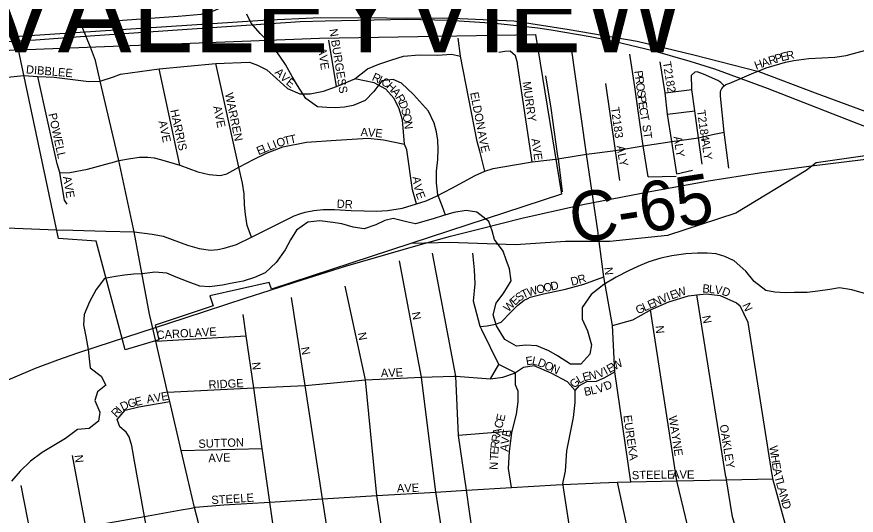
# Model space of a CAD drawing. Extents: x 0 to 34, y -6.2 to 22.
# Drawn here: x 2.51 to 3.469, y 17.811 to 18.38 of the extents above; entities that cross this region are included whole.
import ezdxf

# ---------------------------------------------------------------- set-up
doc = ezdxf.new("R2010")
doc.units = 0
for name, color, linetype in [('GM_X_City_Street', 7, 'Continuous'), ('GM_X_City_Street_Text', 7, 'Continuous'), ('GM_X_Corporation', 7, 'Continuous'), ('GM_X_Corporation_Text', 7, 'Continuous'), ('GM_X_County_Road', 7, 'Continuous'), ('GM_X_County_Road_Text', 7, 'Continuous'), ('GM_X_Minor_River', 7, 'Continuous'), ('GM_X_Rail_Line', 7, 'Continuous'), ('GM_X_Township_Road', 7, 'Continuous'), ('GM_X_Township_Subdivision', 7, 'Continuous'), ('GM_X_Township_Subdivision_Text', 7, 'Continuous')]:
    doc.layers.add(name, color=color, linetype=linetype)

msp = doc.modelspace()

# ---------------------------------------------------------------- linework, layer by layer
at = {"layer": 'GM_X_City_Street'}
for points in [[(2.58326, 18.37289), (2.69443, 18.38081), (2.72099, 18.38315), (2.73498, 18.38687), (2.78346, 18.40786), (2.87838, 18.44987), (3.04807, 18.52343), (3.04898, 18.52384), (3.12264, 18.55594), (3.17213, 18.57942), (3.21354, 18.59511), (3.23863, 18.6055), (3.35942, 18.6571)], [(2.58396, 18.37117), (2.58326, 18.37289), (2.54907, 18.44999), (2.51839, 18.50309), (2.51749, 18.50536)], [(3.35404, 18.31686), (3.35699, 18.31809), (3.36634, 18.32198), (3.3881, 18.32847), (3.39776, 18.3304), (3.41501, 18.33254), (3.44461, 18.33395), (3.45762, 18.33578), (3.47006, 18.33917), (3.48994, 18.34479), (3.54122, 18.36656), (3.5569, 18.37296), (3.56567, 18.37718), (3.57341, 18.38206), (3.58387, 18.39134)], [(2.66181, 18.0409), (2.64419, 18.13468), (2.64164, 18.14703), (2.62676, 18.21598), (2.60565, 18.30649), (2.60014, 18.33007), (2.59458, 18.34525), (2.59153, 18.35267)], [(2.87541, 18.30051), (2.86649, 18.35356)], [(3.04498, 18.20409), (3.03899, 18.22693), (3.03604, 18.23777), (3.01698, 18.33533), (3.01436, 18.3557)], [(3.08217, 18.32649), (3.08202, 18.32745), (3.08005, 18.33566), (3.07381, 18.34092), (3.06757, 18.34059), (3.06067, 18.33928)], [(2.51826, 18.31302), (2.53419, 18.31191), (2.55309, 18.31117), (2.59273, 18.30635), (2.60565, 18.30649), (2.62071, 18.31155), (2.62867, 18.3145), (2.67276, 18.3208), (2.7376, 18.32673), (2.7762, 18.32843), (2.78507, 18.32482), (2.79591, 18.31957), (2.80675, 18.30971), (2.81956, 18.29821), (2.83369, 18.2923), (2.84551, 18.2923), (2.86062, 18.29526), (2.87541, 18.30051), (2.89643, 18.30938), (2.91088, 18.32055), (2.92369, 18.32614), (2.93847, 18.33106), (2.95194, 18.33533), (2.96968, 18.33665), (2.99071, 18.33632), (3.0068, 18.3373), (3.01698, 18.33533)], [(2.69666, 18.21083), (2.67276, 18.3208)], [(2.77839, 18.1286), (2.77329, 18.14209), (2.77148, 18.15459), (2.77033, 18.1656), (2.77016, 18.17794), (2.76819, 18.1901), (2.76408, 18.20836), (2.7376, 18.32673)], [(3.09892, 18.21461), (3.08217, 18.32649)], [(2.41859, 18.30302), (2.42786, 18.30672), (2.49974, 18.31117), (2.51826, 18.31302)], [(2.55947, 18.20229), (2.55637, 18.21247), (2.53419, 18.31191)], [(2.96693, 18.16667), (2.96212, 18.18259), (2.95589, 18.22824), (2.95326, 18.23481), (2.95063, 18.26241), (2.94669, 18.2762), (2.9411, 18.28737), (2.93191, 18.29756), (2.91844, 18.30478), (2.89643, 18.30938)], [(2.61923, 18.21394), (2.62676, 18.21598), (2.64002, 18.21846), (2.65061, 18.21987), (2.66014, 18.22004), (2.66705, 18.21922), (2.67429, 18.21708), (2.69666, 18.21083), (2.71702, 18.20323), (2.72987, 18.19997), (2.7427, 18.19899), (2.7501, 18.2008), (2.76408, 18.20836), (2.78135, 18.21757), (2.79558, 18.22463), (2.81398, 18.23153), (2.84124, 18.23711), (2.87508, 18.23941), (2.91154, 18.24172), (2.92928, 18.23974), (2.95326, 18.23481)], [(2.57438, 18.13649), (2.61214, 18.13547), (2.64419, 18.13468), (2.66492, 18.13206), (2.67133, 18.13107), (2.67741, 18.12959), (2.70539, 18.11939), (2.71853, 18.11561), (2.7314, 18.11374), (2.7399, 18.11462), (2.74714, 18.1161), (2.76112, 18.12021), (2.77839, 18.1286), (2.82723, 18.1531), (2.83348, 18.15541), (2.83973, 18.15722), (2.8496, 18.15902), (2.86029, 18.16017), (2.87328, 18.16001), (2.89203, 18.15919), (2.90716, 18.15853), (2.92065, 18.1582), (2.9338, 18.15902), (2.95074, 18.16182), (2.96693, 18.16667), (2.97788, 18.17021), (2.98972, 18.1753), (3.00732, 18.18452), (3.03363, 18.19915), (3.04498, 18.20409), (3.05419, 18.20688), (3.06553, 18.20902), (3.09892, 18.21461), (3.12884, 18.2179), (3.13064, 18.21821)], [(2.55949, 18.2022), (2.57084, 18.20244), (2.59123, 18.20639), (2.61623, 18.21313), (2.61923, 18.21394)], [(2.56788, 18.16609), (2.56493, 18.17087), (2.55949, 18.2022), (2.55947, 18.20229)], [(2.27548, 18.14751), (2.34571, 18.14522), (2.55571, 18.13699), (2.57438, 18.13649)], [(3.24007, 17.60203), (3.22368, 17.69748), (3.21393, 17.76801), (3.19655, 17.84898), (3.21172, 17.84956), (3.19321, 17.97488), (3.19048, 18.02788), (3.1806, 18.08351), (3.17438, 18.13238), (3.17423, 18.13337)], [(3.05937, 17.59113), (3.03769, 17.7424), (3.02375, 17.83973), (3.01478, 17.90233), (3.01167, 17.96994), (2.98497, 18.11036)], [(3.04158, 18.02267), (3.03969, 18.02652), (3.03194, 18.05539), (3.03367, 18.07548), (3.033, 18.09147), (3.03128, 18.11052)], [(2.98919, 17.83622), (2.98896, 17.83766), (2.97268, 17.96886), (2.94752, 18.10159)], [(3.09407, 18.05875), (3.09668, 18.05996), (3.10426, 18.06213), (3.11184, 18.06375), (3.13701, 18.06916), (3.15786, 18.07485), (3.1806, 18.08351)], [(2.96334, 17.58694), (2.93742, 17.72782), (2.92149, 17.83363), (2.90852, 17.96561), (2.88548, 18.07284)], [(3.19048, 18.02788), (3.21388, 18.03445), (3.23279, 18.04491), (3.23418, 18.04554), (3.25509, 18.05489), (3.27731, 18.06184), (3.28691, 18.06282), (3.29749, 18.0639), (3.31375, 18.0619), (3.33211, 18.05376), (3.33655, 18.05021)], [(3.32028, 17.85514), (3.28691, 18.06282)], [(2.86019, 17.82555), (2.86019, 17.82555), (2.85952, 17.82993), (2.83954, 17.9594), (2.82408, 18.05962)], [(3.03969, 18.02652), (3.04767, 18.02747), (3.05701, 18.0295), (3.06351, 18.03153), (3.07448, 18.0429), (3.0826, 18.05089), (3.08964, 18.05671), (3.09407, 18.05875)], [(3.3066, 17.60722), (3.28493, 17.71335), (3.28155, 17.77778), (3.2641, 17.85059), (3.23418, 18.04554)], [(3.3733, 17.85605), (3.37312, 17.85724), (3.34549, 18.03133), (3.33655, 18.05021)], [(2.77221, 17.57666), (2.74444, 17.70037), (2.7131, 17.8201), (2.70525, 17.85431), (2.69807, 17.88511), (2.68501, 17.94112), (2.68256, 17.95161), (2.66897, 18.00986), (2.6621, 18.03937), (2.66181, 18.0409)], [(2.81498, 17.7179), (2.79947, 17.82635), (2.79072, 17.88755), (2.78086, 17.95649), (2.77232, 18.01618), (2.76887, 18.04034)], [(2.66897, 18.00986), (2.77232, 18.01618)], [(3.1351, 17.8404), (3.13477, 17.84263), (3.13422, 17.84621), (3.13402, 17.84753), (3.13701, 17.86138), (3.13864, 17.88466), (3.14622, 17.92283), (3.14812, 17.93989), (3.14812, 17.9537), (3.13918, 17.96344), (3.12062, 17.97335), (3.10128, 17.98185), (3.08909, 17.97969), (3.07989, 17.97373), (3.06094, 17.98321), (3.04158, 18.02267)], [(3.0512, 17.96696), (3.06094, 17.98321)], [(2.68256, 17.95161), (2.78086, 17.95649), (2.83954, 17.9594), (2.90852, 17.96561), (2.97268, 17.96886), (3.00935, 17.96988)], [(3.00935, 17.96988), (3.01167, 17.96994), (3.0512, 17.96696), (3.06554, 17.96872), (3.07989, 17.97373)], [(3.0754, 17.84281), (3.07189, 17.86457), (3.07285, 17.88392), (3.07574, 17.90512), (3.07625, 17.90723), (3.08092, 17.92663), (3.08285, 17.94063), (3.08283, 17.9528), (3.08141, 17.95626), (3.08001, 17.9601), (3.07989, 17.97373)], [(3.14812, 17.9537), (3.15286, 17.95948), (3.16133, 17.96378), (3.17235, 17.96422), (3.1812, 17.96814), (3.19321, 17.97488)], [(2.62493, 17.92068), (2.6341, 17.93099), (2.64974, 17.93496), (2.68501, 17.94112)], [(2.64391, 17.87736), (2.64151, 17.89055), (2.63878, 17.90089), (2.63513, 17.90594), (2.6281, 17.91223), (2.62493, 17.92068)], [(3.07625, 17.90723), (3.01478, 17.90233)], [(2.69807, 17.88511), (2.79072, 17.88755)], [(2.63357, 17.5687), (2.60917, 17.68894), (2.58905, 17.79807), (2.57401, 17.87961)], [(2.7, 17.57023), (2.67739, 17.69404), (2.65622, 17.81), (2.64396, 17.87712), (2.64391, 17.87736)], [(3.21172, 17.84956), (3.2641, 17.85059), (3.32083, 17.85171), (3.37382, 17.85275)], [(3.36005, 17.6082), (3.34153, 17.72315), (3.33463, 17.78614), (3.32761, 17.80952), (3.32083, 17.85171), (3.32029, 17.85504), (3.32028, 17.85514)], [(3.41507, 17.61242), (3.39298, 17.73206), (3.38982, 17.79493), (3.37382, 17.85275), (3.3733, 17.85605)], [(2.56749, 17.5648), (2.54692, 17.68517), (2.52681, 17.78702), (2.51532, 17.84523)], [(2.69797, 17.81741), (2.70763, 17.81913), (2.7131, 17.8201), (2.71459, 17.82036), (2.74694, 17.82321), (2.79947, 17.82635), (2.85952, 17.82993), (2.92149, 17.83363), (2.98896, 17.83766), (3.02375, 17.83973), (3.0754, 17.84281), (3.12638, 17.84586), (3.13422, 17.84621), (3.17658, 17.84809)], [(3.17658, 17.84809), (3.19655, 17.84898)], [(3.02937, 17.59064), (3.00466, 17.7376), (2.98928, 17.8356), (2.98919, 17.83622)], [(3.17475, 17.59844), (3.15759, 17.69298), (3.14763, 17.75831), (3.1351, 17.8404)], [(2.8978, 17.58173), (2.87664, 17.71894), (2.86019, 17.82555)], [(2.27548, 17.76316), (2.31635, 17.79028), (2.32948, 17.79788), (2.33448, 17.79877), (2.33863, 17.79951), (2.35267, 17.79947), (2.4, 17.7901), (2.45191, 17.77983), (2.46754, 17.77573), (2.47959, 17.77863), (2.52681, 17.78702), (2.58905, 17.79807), (2.65622, 17.81), (2.69797, 17.81741)]]:
    msp.add_lwpolyline(points, dxfattribs=at)
at = {"layer": 'GM_X_Corporation'}
for points in [[(2.27548, 18.3425), (2.79124, 18.37642), (2.85711, 18.37932), (3.00794, 18.37862), (3.07787, 18.3756), (3.14119, 18.36559), (3.21895, 18.35224), (3.28339, 18.33668), (3.35782, 18.31778), (3.42225, 18.29333), (3.49446, 18.26666)], [(3.49245, 18.22341), (3.43665, 18.2152), (3.42314, 18.21343), (3.41167, 18.20469), (3.3317, 18.15582), (3.25354, 18.1305), (3.18775, 18.12365), (3.13686, 18.12348), (3.07985, 18.11996), (3.00426, 18.12245), (2.9915, 18.12214), (2.96044, 18.12141), (2.80121, 18.06942), (2.79837, 18.077), (2.73089, 18.06148), (2.73468, 18.05012), (2.66838, 18.02834), (2.66938, 18.02424), (2.67248, 18.01149), (2.63421, 17.99991), (2.60083, 18.1241), (2.55811, 18.12715), (2.51209, 18.34231), (2.27548, 18.32497)]]:
    msp.add_lwpolyline(points, dxfattribs=at)
msp.add_lwpolyline([(2.51209, 18.34231), (2.85609, 18.35581), (3.10288, 18.3599), (3.13239, 18.17754), (2.96044, 18.12141), (2.80121, 18.06942), (2.79837, 18.077), (2.73089, 18.06148), (2.73468, 18.05012), (2.66838, 18.02834), (2.66938, 18.02424), (2.67248, 18.01149), (2.63421, 17.99991), (2.60083, 18.1241), (2.55811, 18.12715)], close=True, dxfattribs=at)
at = {"layer": 'GM_X_County_Road'}
for points in [[(2.59153, 18.35267), (2.58915, 18.35846), (2.58396, 18.37117)], [(3.13064, 18.21821), (3.16102, 18.22348), (3.19404, 18.22759), (3.2258, 18.233), (3.25841, 18.23766), (3.28887, 18.24188), (3.30495, 18.24578), (3.31801, 18.24831), (3.31402, 18.28954), (3.31389, 18.294), (3.31451, 18.29601), (3.31548, 18.29817), (3.3181, 18.30131), (3.32018, 18.30275), (3.3248, 18.30453), (3.35224, 18.31611), (3.35404, 18.31686)], [(3.17423, 18.13337), (3.16102, 18.22348)]]:
    msp.add_lwpolyline(points, dxfattribs=at)
at = {"layer": 'GM_X_Minor_River'}
for points in [[(3.00007, 18.15386), (2.99608, 18.16421), (2.99132, 18.17681), (2.98961, 18.1905), (2.98979, 18.20379), (2.99112, 18.21743), (2.99166, 18.2292), (2.99104, 18.23946), (2.98965, 18.24897), (2.98713, 18.25888), (2.98049, 18.27225), (2.96332, 18.29147), (2.94985, 18.30419), (2.94005, 18.3085), (2.92715, 18.30716), (2.91789, 18.29476), (2.90827, 18.28464), (2.89455, 18.27875), (2.88467, 18.27699), (2.87443, 18.27637), (2.86458, 18.2765), (2.8536, 18.27741), (2.84046, 18.28671), (2.83081, 18.30165), (2.82489, 18.31198), (2.81712, 18.32575), (2.8108, 18.33533), (2.80187, 18.34722), (2.78841, 18.36108), (2.77797, 18.37299), (2.77317, 18.38293)], [(3.11776, 17.9989), (3.1042, 18.00478), (3.0917, 18.00533), (3.08107, 18.00434), (3.06753, 18.01174), (3.05827, 18.02743), (3.05427, 18.04002), (3.05786, 18.05326), (3.06673, 18.06491), (3.07488, 18.07884), (3.07318, 18.09254), (3.06915, 18.10284), (3.06587, 18.11276), (3.05581, 18.12581), (3.0533, 18.13571), (3.04927, 18.1464), (3.03578, 18.15721), (3.02367, 18.1589), (3.00962, 18.15681), (2.99668, 18.15282), (2.98717, 18.14991), (2.97499, 18.14666), (2.96548, 18.14375), (2.95528, 18.14617), (2.94017, 18.14979), (2.93067, 18.14765), (2.92037, 18.14285), (2.90704, 18.1381), (2.89456, 18.14017), (2.88134, 18.14377), (2.87114, 18.14543), (2.85638, 18.14715), (2.84272, 18.14582), (2.8297, 18.1365), (2.82273, 18.12559), (2.81689, 18.11428), (2.80646, 18.09961), (2.7938, 18.08802), (2.7816, 18.08249), (2.76866, 18.07849), (2.75612, 18.076), (2.7451, 18.07387), (2.73029, 18.0718), (2.71931, 18.07271), (2.70611, 18.07745), (2.69216, 18.08295), (2.68161, 18.08765), (2.66798, 18.0886), (2.65394, 18.0869), (2.64408, 18.08627), (2.63345, 18.08528), (2.6232, 18.0839), (2.61028, 18.08142), (2.60102, 18.06901), (2.59324, 18.05469), (2.58736, 18.04035), (2.58644, 18.02859), (2.58929, 18.01526), (2.59174, 18.00042), (2.59312, 17.98977), (2.59411, 17.9795), (2.60649, 17.96984), (2.61204, 17.95989), (2.60246, 17.95205), (2.59929, 17.94222), (2.60517, 17.92885), (2.60352, 17.91863), (2.5928, 17.91042), (2.57951, 17.90908), (2.56611, 17.89901), (2.55274, 17.89084), (2.53937, 17.88305), (2.52596, 17.87298), (2.51406, 17.86138), (2.50443, 17.85012)], [(3.47831, 18.06419), (3.46397, 18.06856), (3.44997, 18.07065), (3.43896, 18.06891), (3.42529, 18.06682), (3.41314, 18.06547), (3.39836, 18.06529), (3.38812, 18.06505), (3.37601, 18.06598), (3.3658, 18.06763), (3.35229, 18.07807), (3.34298, 18.08997), (3.32949, 18.10154), (3.31895, 18.10662), (3.30914, 18.10942), (3.29891, 18.11032), (3.28755, 18.11047), (3.27427, 18.10952), (3.25832, 18.10746), (3.24578, 18.10459), (3.23208, 18.1006), (3.2195, 18.09508), (3.20882, 18.09029), (3.1947, 18.08289), (3.18057, 18.07473), (3.16638, 18.06316), (3.15595, 18.04849), (3.15615, 18.0352), (3.16203, 18.02183), (3.16674, 18.00582), (3.1647, 17.99522), (3.15431, 17.98359), (3.14257, 17.98375), (3.12791, 17.99307), (3.11776, 17.9989)]]:
    msp.add_lwpolyline(points, dxfattribs=at)
at = {"layer": 'GM_X_Rail_Line'}
for points in [[(2.27548, 18.33657), (2.39905, 18.34495), (2.47587, 18.35024), (2.53185, 18.35394), (2.58833, 18.35789), (2.69389, 18.36504), (2.83393, 18.37456), (2.86258, 18.37563), (2.95579, 18.37739), (3.00379, 18.37613), (3.05674, 18.37285), (3.10544, 18.36744), (3.12078, 18.36529), (3.16527, 18.35745), (3.19231, 18.35218), (3.23685, 18.3415), (3.27896, 18.32957), (3.30729, 18.32066), (3.36713, 18.29855), (3.45795, 18.26329), (3.54826, 18.22812)], [(2.27548, 17.81575), (2.37479, 17.88597), (2.477, 17.95594), (2.53177, 17.97907), (2.55733, 17.98858), (2.58005, 17.9966), (2.60104, 18.00352), (2.70241, 18.03673), (2.77241, 18.0592), (2.79871, 18.06772), (2.82797, 18.07735), (2.88587, 18.09552), (2.9687, 18.11951), (3.00564, 18.12958), (3.04219, 18.13884), (3.08725, 18.1502), (3.15689, 18.16575), (3.23364, 18.18084), (3.30011, 18.19279), (3.35839, 18.20193), (3.41471, 18.20971), (3.49877, 18.21983)]]:
    msp.add_lwpolyline(points, dxfattribs=at)
at = {"layer": 'GM_X_Township_Road'}
msp.add_lwpolyline([(3.16102, 18.22348), (3.14312, 18.34946)], dxfattribs=at)
at = {"layer": 'GM_X_Township_Subdivision'}
for points in [[(3.216, 18.30015), (3.21058, 18.3375)], [(3.26413, 18.20101), (3.25841, 18.23766), (3.25354, 18.26902), (3.2509, 18.2932), (3.24521, 18.32855)], [(3.12837, 18.22111), (3.12046, 18.27571), (3.11455, 18.31266)], [(3.28107, 18.2978), (3.28104, 18.31331), (3.28481, 18.31685)], [(3.3181, 18.30131), (3.31445, 18.30504), (3.31114, 18.30735), (3.29464, 18.31471), (3.28743, 18.3172), (3.28481, 18.31685)], [(3.19896, 18.19342), (3.19404, 18.22759), (3.1832, 18.3038)], [(3.23125, 18.19751), (3.2258, 18.233), (3.22076, 18.26733), (3.216, 18.30015)], [(3.2509, 18.2932), (3.28107, 18.2972), (3.28107, 18.2978)], [(3.29294, 18.21203), (3.28887, 18.24188), (3.28468, 18.27262), (3.28107, 18.2972)], [(3.25354, 18.26902), (3.28468, 18.27262)], [(3.32359, 18.2074), (3.31801, 18.24831)], [(3.1336, 18.18029), (3.12884, 18.2179), (3.12837, 18.22111)], [(3.23125, 18.19751), (3.26337, 18.19822)], [(3.26413, 18.20101), (3.28192, 18.20504)]]:
    msp.add_lwpolyline(points, dxfattribs=at)

# ---------------------------------------------------------------- texts
at = {"layer": 'GM_X_City_Street_Text'}
for s, rotation, p in [('N BURGESS', 279.08813, (2.86718, 18.36573)), ('AVE', 277.85664, (2.85437, 18.3443)), ('E', 14.1025, (3.38376, 18.32916)), ('R', 12.45769, (3.39016, 18.33077)), ('H', 20.59186, (3.35479, 18.31949)), ('A', 18.91874, (3.36253, 18.3224)), ('R', 17.15987, (3.37034, 18.32508)), ('P', 16.62857, (3.37748, 18.32728)), ('DIBBLEE', 355.15712, (2.52053, 18.31556)), ('A', 316.32935, (2.80421, 18.31583)), ('V', 316.30557, (2.81024, 18.31008)), ('R', 336.06464, (2.91515, 18.30797)), ('I', 333.92381, (2.92192, 18.30497)), ('E', 322.02701, (2.81705, 18.30365)), ('C', 330.27319, (2.92552, 18.30321)), ('H', 316.60745, (2.93156, 18.29985)), ('MURRY', 277.81547, (3.08801, 18.30569)), ('WARREN', 281.69062, (2.74799, 18.29248)), ('A', 308.8373, (2.93738, 18.29437)), ('R', 299.98893, (2.94239, 18.2882)), ('ELDON', 281.07399, (3.02799, 18.29329)), ('D', 292.6619, (2.946, 18.28199)), ('HARRIS', 282.40935, (2.68549, 18.27333)), ('AVE', 281.69062, (2.73454, 18.27751)), ('S', 284.63927, (2.9491, 18.27463)), ('POWELL', 282.30899, (2.54632, 18.26916)), ('O', 281.0399, (2.95075, 18.26834)), ('AVE', 282.09583, (2.67206, 18.26074)), ('N', 276.55022, (2.95231, 18.26035)), ('T', 12.5851, (2.81634, 18.23363)), ('T', 12.27986, (2.82283, 18.23508)), ('A', 359.03824, (2.90287, 18.2439)), ('V', 355.12019, (2.91103, 18.24377)), ('E', 354.00672, (2.91929, 18.24306)), ('A', 281.19423, (3.03633, 18.24911)), ('L', 22.0327, (2.79877, 18.2271)), ('I', 22.00438, (2.80495, 18.2296)), ('O', 18.11015, (2.80865, 18.2311)), ('V', 281.17279, (3.03795, 18.24093)), ('AVE', 277.84924, (3.09802, 18.24069)), ('E', 22.01452, (2.78641, 18.2221)), ('L', 22.01452, (2.79259, 18.2246)), ('E', 283.08537, (3.03964, 18.23242)), ('AVE', 279.78342, (2.563, 18.19742)), ('A', 277.01117, (2.96218, 18.19731)), ('V', 282.6852, (2.96337, 18.18803)), ('E', 290.72596, (2.96562, 18.17851)), ('DR', 356.98902, (2.87551, 18.16222)), ('N', 275.70628, (3.18135, 18.09396)), ('D', 14.44981, (3.14417, 18.07301)), ('R', 16.75735, (3.15263, 18.0752)), ('W', 16.55271, (3.09456, 18.06087)), ('O', 13.05031, (3.1048, 18.06391)), ('O', 12.51458, (3.1129, 18.06579)), ('D', 12.53504, (3.12104, 18.0676)), ('W', 19.07821, (3.26456, 18.05967)), ('B', 355.21014, (3.29305, 18.06556)), ('L', 355.18645, (3.30052, 18.06493)), ('V', 351.40007, (3.307, 18.06439)), ('D', 339.64347, (3.31474, 18.06327)), ('E', 43.28067, (3.07929, 18.05012)), ('S', 36.25236, (3.08391, 18.0545)), ('T', 24.92777, (3.08886, 18.05819)), ('V', 23.66066, (3.24693, 18.05271)), ('I', 20.9245, (3.25445, 18.05601)), ('E', 19.23847, (3.25828, 18.05748)), ('W', 44.76226, (3.07164, 18.04254)), ('L', 24.30477, (3.22721, 18.04381)), ('E', 24.32077, (3.23329, 18.04655)), ('N', 24.28655, (3.23936, 18.0493)), ('N', 293.97376, (3.3387, 18.05117)), ('N', 281.30154, (2.96133, 18.04247)), ('G', 24.30647, (3.21962, 18.04038)), ('N', 281.30574, (3.29299, 18.0383)), ('CAROL', 3.65478, (2.6703, 18.01223)), ('AVE', 3.9426, (2.71362, 18.01473)), ('N', 275.70844, (3.23968, 18.02729)), ('N', 281.32255, (2.89966, 18.01913)), ('N', 281.30154, (2.83466, 18.00247)), ('N', 275.70844, (2.77885, 17.98563)), ('E', 9.85761, (3.0925, 17.98219)), ('L', 348.66863, (3.09815, 17.98334)), ('D', 338.04434, (3.10424, 17.98216)), ('O', 334.80353, (3.11184, 17.9791)), ('W', 28.73254, (3.19298, 17.97642)), ('AVE', 1.9739, (2.92619, 17.9689)), ('N', 334.77444, (3.11938, 17.97556)), ('N', 8.13628, (3.16403, 17.96567)), ('V', 22.83875, (3.17483, 17.96755)), ('I', 28.3678, (3.18341, 17.97121)), ('E', 28.58017, (3.18711, 17.97322)), ('RIDGE', 2.72483, (2.7295, 17.95557)), ('G', 44.67542, (3.14721, 17.95558)), ('L', 28.56903, (3.15258, 17.96102)), ('E', 15.08979, (3.15789, 17.96399)), ('B', 11.96245, (3.1592, 17.94726)), ('L', 12.82607, (3.16669, 17.94884)), ('V', 17.0298, (3.17391, 17.95052)), ('D', 24.95024, (3.18319, 17.95346)), ('AVE', 9.77736, (2.65928, 17.93887)), ('D', 26.48684, (2.63125, 17.93026)), ('G', 13.77118, (2.63819, 17.93379)), ('E', 13.03557, (2.64625, 17.93577)), ('R', 46.63167, (2.62394, 17.92231)), ('I', 46.57655, (2.62909, 17.92776)), ('C', 70.8509, (3.06392, 17.9094)), ('E', 77.3478, (3.06671, 17.91762)), ('EUREKA', 278.27526, (3.20301, 17.92487)), ('WAYNE', 278.91453, (3.25467, 17.92406)), ('A', 80.60236, (3.06267, 17.90159)), ('E', 76.32151, (3.07329, 17.89976)), ('OAKLEY', 279.1291, (3.31301, 17.91407)), ('SUTTON', 2.08141, (2.71785, 17.88807)), ('R', 80.60952, (3.06145, 17.89419)), ('V', 82.94545, (3.07232, 17.89177)), ('R', 83.13406, (3.06056, 17.88686)), ('A', 84.85701, (3.07158, 17.88356)), ('W', 278.81007, (3.36967, 17.88988)), ('AVE', 1.9739, (2.72925, 17.87178)), ('T', 87.34905, (3.05996, 17.87372)), ('E', 87.35265, (3.06027, 17.88038)), ('N', 275.72791, (2.57635, 17.87979)), ('N', 87.35476, (3.05946, 17.8629)), ('H', 278.79768, (3.37133, 17.87918)), ('E', 278.81606, (3.37261, 17.87094)), ('STEELE', 1.14515, (3.21288, 17.85223)), ('AVE', 0.00001, (3.25875, 17.85307)), ('A', 280.71902, (3.37369, 17.86401)), ('T', 285.2563, (3.37542, 17.85503)), ('AVE', 1.9739, (2.94452, 17.83723)), ('L', 285.8307, (3.37721, 17.8485)), ('A', 285.80728, (3.37903, 17.84209)), ('STEELE', 3.43258, (2.73281, 17.8239)), ('N', 285.81386, (3.3813, 17.83407)), ('D', 285.81386, (3.38357, 17.82605))]:
    msp.add_text(s, height=0.00947, rotation=rotation, dxfattribs=at).set_placement(p)
at = {"layer": 'GM_X_Corporation_Text'}
msp.add_text('VALLEYVIEW', height=0.094697, rotation=0.00001, dxfattribs=at).set_placement((2.47251, 18.33948))
at = {"layer": 'GM_X_County_Road_Text'}
msp.add_text('C-65', height=0.056818, rotation=8.69603, dxfattribs=at).set_placement((3.14597, 18.12117))
at = {"layer": 'GM_X_Township_Subdivision_Text'}
for s, rotation, p in [('T2182', 279.46332, (3.24797, 18.32824)), ('P', 277.50799, (3.21551, 18.31818)), ('R', 277.47749, (3.21639, 18.31157)), ('O', 277.49527, (3.21736, 18.30413)), ('S', 277.49886, (3.21845, 18.29587)), ('P', 277.4809, (3.21932, 18.28926)), ('E', 277.49886, (3.22019, 18.28265)), ('T2183', 277.90899, (3.18882, 18.27652)), ('C', 277.98747, (3.22107, 18.27595)), ('T2184', 277.90899, (3.28715, 18.27319)), ('T', 281.39314, (3.22222, 18.26792)), ('ST', 277.13512, (3.22468, 18.2565)), ('ALY', 277.84822, (3.26049, 18.24319)), ('ALY', 277.85664, (3.29215, 18.23986)), ('A', 275.97813, (3.19551, 18.23269)), ('L', 281.31856, (3.19653, 18.22345)), ('Y', 281.77049, (3.19785, 18.21683))]:
    msp.add_text(s, height=0.00947, rotation=rotation, dxfattribs=at).set_placement(p)

doc.saveas('drawing.dxf')
